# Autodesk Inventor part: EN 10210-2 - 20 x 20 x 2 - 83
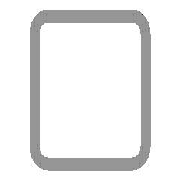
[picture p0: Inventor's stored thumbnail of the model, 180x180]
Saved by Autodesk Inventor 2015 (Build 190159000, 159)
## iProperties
Created: 2014-02
Part Number: EN 10210-2 - 20 x 20 x 2 - 83
Material: Steel, Mild
Description: Tube
Document SubType Name: Modeling
Standard: DIN
Designer: TREINA6
Standard Revision: 1997
Standards Organization: DIN
Language: en-US
Size Designation: 20 x 20 x 2
Categories: <MemberInstance><Categories><Category DisplayName="Structural Shapes" InternalName="089c4875-fa83-4c05-b084-43b9cc11f5ed" Mnemonic="GRDR"><CategoryParameter Dis
Stock Number: 20 x 20 x 2
Density: 7.85 g/cm^3
Appearance: Semi-Polished
IsCustomPart: 1
_CCFamilyMember: 1
_CCFamilyDisplayName: DIN EN 10210-2 (Square) - Tube
_FrameMemberDoc: Frame Member File
_Version: 15.0.0
_GetPNFromCC: 1
Author: TREINA6
G_L: 83,000 mm
G_W: 20,000 mm
G_H: 20,000 mm
+ECC72DE1-4717-413D-80C3-65A0A80F5B11+CUTDETAIL1: Cut
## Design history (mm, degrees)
node "Start plane"
node "End plane"
sketch "Sketch"
  geometry: L1 (-10, -7)-(-10, 7); L2 (-7, 10)-(7, 10); L3 (10, 7)-(10, -7); L4 (7, -10)-(-7, -10); L5 (-7, 8)-(7, 8); L6 (8, 7)-(8, -7); L7 (7, -8)-(-7, -8); L8 (-8, -7)-(-8, 7); L9 (0, 14.87)-(0, -14.87) reference; L10 (-14.87, 0)-(14.87, 0) reference; A1 r 3 centre (-7, -7) between (-10, -7) and (-7, -10); A2 r 3 centre (-7, 7) between (-7, 10) and (-10, 7); A3 r 3 centre (7, 7) between (10, 7) and (7, 10); A4 r 3 centre (7, -7) between (7, -10) and (10, -7); A5 r 1 centre (-7, 7) between (-7, 8) and (-8, 7); A6 r 1 centre (7, 7) between (8, 7) and (7, 8); A7 r 1 centre (7, -7) between (7, -8) and (8, -7); A8 r 1 centre (-7, -7) between (-8, -7) and (-7, -8)
  constraints: 16 end point, 16 point on circle, 8 centre point, 8 tangent, 4 parallel, 3 equal radius, 2 perpendicular, 7 other
  dimensions: "d7" = 3 radius of A1 (= G_IR); "d10" = 20 distance between parallel lines of L2 L4 (= G_H); "d11" = 20 distance between parallel lines of L1 L3 (= G_W); "d12" = 2 distance between parallel lines of L3 L6 (= G_T); "d15" = 10 distance between parallel lines of L2 L10 (= 0.5 x d10); "d16" = 10 distance between parallel lines of L9 L3 (= 0.5 x d11)
extrude "Body" new body sketch "Sketch" stored distance "d3" = 83 (= G_L); taper "d4" = 0 deg
node "Driven Length"
  sketch "Sketch3"
    geometry: L1 (0, 0)-(10, 0) reference
    constraints: 2 end point, 1 horizontal
  workplane "Work Plane3"
  sketch "Sketch4"
    geometry: L1 (-2, 20)-(12, 20) reference; L2 (-2, 103)-(12, 103) reference
    dimensions: "d18" = 83 distance between parallel lines of L1 L2 (derived)
workplane "Work Plane4"
split "Split1"
body "Solid1"
other parameters: "G_W" = 20 [user parameter; used in 1 equation term], "G_H" = 20 [user parameter; used in 1 equation term], "G_T" = 2 [user parameter; used in 1 equation term], "G_IR" = 3 [user parameter; used in 1 equation term], "G_L" = 83 (= d18) [user parameter; used in 1 equation term], "G_OFFSET_END" = 0 [user parameter; used in 1 equation term], "d14" = 103 (= G_OFFSET_END + B_L), "B_L" = 103 [user parameter; used in 1 equation term], "d17" = 90 deg
